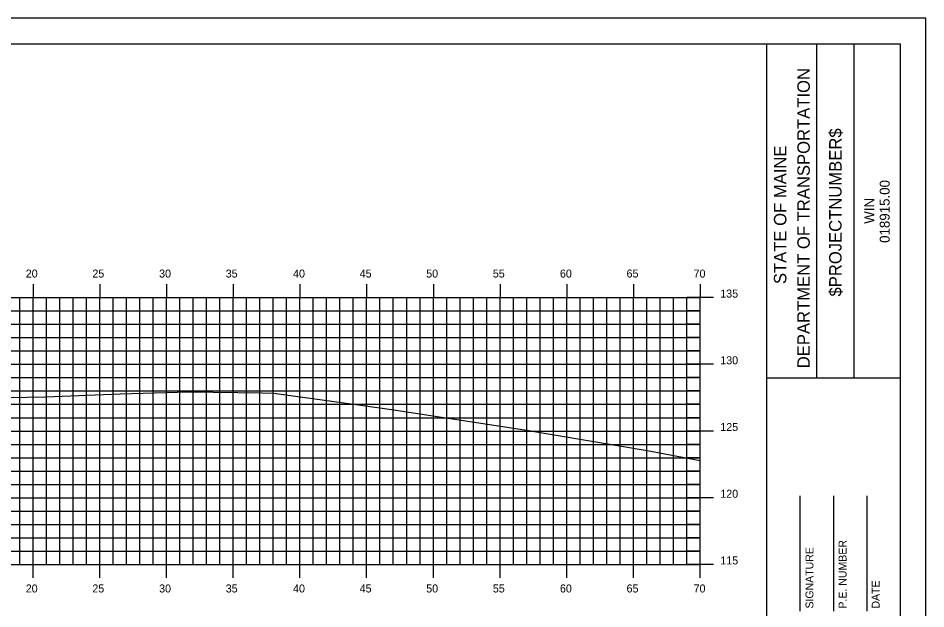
# Model space of a CAD drawing. Extents: x 851517 to 851688, y 365624 to 365734.
# Drawn here: x 851618.7 to 851686.7, y 365689.7 to 365734 of the extents above; entities that cross this region are included whole.
import ezdxf

# ---------------------------------------------------------------- set-up
doc = ezdxf.new("R2010")
doc.units = 0
for name, color, linetype in [('BORDER', 7, 'Continuous'), ('H_V ANNOTATION', 7, 'Continuous'), ('MAJOR', 7, 'Continuous'), ('MINOR', 7, 'Continuous'), ('PLOT BOUNDARY', 7, 'Continuous'), ('S_Roadway_Centerline', 7, 'Continuous')]:
    doc.layers.add(name, color=color, linetype=linetype)

msp = doc.modelspace()

# ---------------------------------------------------------------- linework, layer by layer
at = {"layer": 'BORDER'}
for p, q in [((851674.766, 365627.027), (851674.766, 365732.027)), ((851678.494, 365707.024), (851678.494, 365732.024)), ((851681.289, 365707.024), (851681.289, 365732.024)), ((851674.767, 365707.021), (851684.766, 365707.021)), ((851677.266, 365689.53), (851677.266, 365698.177)), ((851679.766, 365689.53), (851679.766, 365698.177)), ((851682.266, 365689.53), (851682.266, 365698.177))]:
    msp.add_line(p, q, dxfattribs=at)
msp.add_lwpolyline([(851524.766, 365627.027), (851684.766, 365627.027), (851684.766, 365732.027), (851524.766, 365732.027)], close=True, dxfattribs=at)
at = {"layer": 'MAJOR'}
for p, q in [((851619.766, 365714.029), (851619.766, 365713.027)), ((851624.766, 365714.029), (851624.766, 365713.027)), ((851629.766, 365714.029), (851629.766, 365713.027)), ((851634.766, 365714.029), (851634.766, 365713.027)), ((851639.766, 365714.029), (851639.766, 365713.027)), ((851644.766, 365714.029), (851644.766, 365713.027)), ((851649.766, 365714.029), (851649.766, 365713.027)), ((851654.766, 365714.029), (851654.766, 365713.027)), ((851659.766, 365714.029), (851659.766, 365713.027)), ((851664.766, 365714.029), (851664.766, 365713.027)), ((851669.766, 365714.029), (851669.766, 365713.027)), ((851529.766, 365713.027), (851669.766, 365713.027)), ((851529.766, 365713.027), (851669.766, 365713.027)), ((851619.766, 365693.027), (851619.766, 365713.027)), ((851624.766, 365693.027), (851624.766, 365713.027)), ((851629.766, 365693.027), (851629.766, 365713.027)), ((851634.766, 365693.027), (851634.766, 365713.027)), ((851639.766, 365693.027), (851639.766, 365713.027)), ((851644.766, 365693.027), (851644.766, 365713.027)), ((851649.766, 365693.027), (851649.766, 365713.027)), ((851654.766, 365693.027), (851654.766, 365713.027)), ((851659.766, 365693.027), (851659.766, 365713.027)), ((851664.766, 365693.027), (851664.766, 365713.027)), ((851670.768, 365713.027), (851668.764, 365713.027)), ((851669.766, 365693.027), (851669.766, 365713.027)), ((851669.766, 365693.027), (851669.766, 365713.027)), ((851529.766, 365708.027), (851669.766, 365708.027)), ((851670.768, 365708.027), (851668.764, 365708.027)), ((851529.766, 365703.027), (851669.766, 365703.027)), ((851670.768, 365703.027), (851668.764, 365703.027)), ((851529.766, 365698.027), (851669.766, 365698.027)), ((851670.768, 365698.027), (851668.764, 365698.027)), ((851529.766, 365693.027), (851669.766, 365693.027)), ((851529.766, 365693.027), (851669.766, 365693.027)), ((851619.766, 365692.025), (851619.766, 365693.027)), ((851624.766, 365692.025), (851624.766, 365693.027)), ((851629.766, 365692.025), (851629.766, 365693.027)), ((851634.766, 365692.025), (851634.766, 365693.027)), ((851639.766, 365692.025), (851639.766, 365693.027)), ((851644.766, 365692.025), (851644.766, 365693.027)), ((851649.766, 365692.025), (851649.766, 365693.027)), ((851654.766, 365692.025), (851654.766, 365693.027)), ((851659.766, 365692.025), (851659.766, 365693.027)), ((851664.766, 365692.025), (851664.766, 365693.027)), ((851670.768, 365693.027), (851668.764, 365693.027)), ((851669.766, 365692.025), (851669.766, 365693.027))]:
    msp.add_line(p, q, dxfattribs=at)
at = {"layer": 'MINOR'}
for p, q in [((851618.766, 365693.027), (851618.766, 365713.027)), ((851620.766, 365693.027), (851620.766, 365713.027)), ((851621.766, 365693.027), (851621.766, 365713.027)), ((851622.766, 365693.027), (851622.766, 365713.027)), ((851623.766, 365693.027), (851623.766, 365713.027)), ((851625.766, 365693.027), (851625.766, 365713.027)), ((851626.766, 365693.027), (851626.766, 365713.027)), ((851627.766, 365693.027), (851627.766, 365713.027)), ((851628.766, 365693.027), (851628.766, 365713.027)), ((851630.766, 365693.027), (851630.766, 365713.027)), ((851631.766, 365693.027), (851631.766, 365713.027)), ((851632.766, 365693.027), (851632.766, 365713.027)), ((851633.766, 365693.027), (851633.766, 365713.027)), ((851635.766, 365693.027), (851635.766, 365713.027)), ((851636.766, 365693.027), (851636.766, 365713.027)), ((851637.766, 365693.027), (851637.766, 365713.027)), ((851638.766, 365693.027), (851638.766, 365713.027)), ((851640.766, 365693.027), (851640.766, 365713.027)), ((851641.766, 365693.027), (851641.766, 365713.027)), ((851642.766, 365693.027), (851642.766, 365713.027)), ((851643.766, 365693.027), (851643.766, 365713.027)), ((851645.766, 365693.027), (851645.766, 365713.027)), ((851646.766, 365693.027), (851646.766, 365713.027)), ((851647.766, 365693.027), (851647.766, 365713.027)), ((851648.766, 365693.027), (851648.766, 365713.027)), ((851650.766, 365693.027), (851650.766, 365713.027)), ((851651.766, 365693.027), (851651.766, 365713.027)), ((851652.766, 365693.027), (851652.766, 365713.027)), ((851653.766, 365693.027), (851653.766, 365713.027)), ((851655.766, 365693.027), (851655.766, 365713.027)), ((851656.766, 365693.027), (851656.766, 365713.027)), ((851657.766, 365693.027), (851657.766, 365713.027)), ((851658.766, 365693.027), (851658.766, 365713.027)), ((851660.766, 365693.027), (851660.766, 365713.027)), ((851661.766, 365693.027), (851661.766, 365713.027)), ((851662.766, 365693.027), (851662.766, 365713.027)), ((851663.766, 365693.027), (851663.766, 365713.027)), ((851665.766, 365693.027), (851665.766, 365713.027)), ((851666.766, 365693.027), (851666.766, 365713.027)), ((851667.766, 365693.027), (851667.766, 365713.027)), ((851668.766, 365693.027), (851668.766, 365713.027)), ((851529.766, 365712.027), (851669.766, 365712.027)), ((851669.766, 365712.027), (851668.764, 365712.027)), ((851529.766, 365711.027), (851669.766, 365711.027)), ((851669.766, 365711.027), (851668.764, 365711.027)), ((851529.766, 365710.027), (851669.766, 365710.027)), ((851669.766, 365710.027), (851668.764, 365710.027)), ((851529.766, 365709.027), (851669.766, 365709.027)), ((851669.766, 365709.027), (851668.764, 365709.027)), ((851529.766, 365707.027), (851669.766, 365707.027)), ((851669.766, 365707.027), (851668.764, 365707.027)), ((851529.766, 365706.027), (851669.766, 365706.027)), ((851669.766, 365706.027), (851668.764, 365706.027)), ((851529.766, 365705.027), (851669.766, 365705.027)), ((851669.766, 365705.027), (851668.764, 365705.027)), ((851529.766, 365704.027), (851669.766, 365704.027)), ((851669.766, 365704.027), (851668.764, 365704.027)), ((851529.766, 365702.027), (851669.766, 365702.027)), ((851669.766, 365702.027), (851668.764, 365702.027)), ((851529.766, 365701.027), (851669.766, 365701.027)), ((851669.766, 365701.027), (851668.764, 365701.027)), ((851529.766, 365700.027), (851669.766, 365700.027)), ((851669.766, 365700.027), (851668.764, 365700.027)), ((851529.766, 365699.027), (851669.766, 365699.027)), ((851669.766, 365699.027), (851668.764, 365699.027)), ((851529.766, 365697.027), (851669.766, 365697.027)), ((851669.766, 365697.027), (851668.764, 365697.027)), ((851529.766, 365696.027), (851669.766, 365696.027)), ((851669.766, 365696.027), (851668.764, 365696.027)), ((851529.766, 365695.027), (851669.766, 365695.027)), ((851669.766, 365695.027), (851668.764, 365695.027)), ((851529.766, 365694.027), (851669.766, 365694.027)), ((851669.766, 365694.027), (851668.764, 365694.027))]:
    msp.add_line(p, q, dxfattribs=at)
at = {"layer": 'PLOT BOUNDARY'}
msp.add_lwpolyline([(851516.673, 365623.968), (851686.673, 365623.968), (851686.673, 365733.968), (851516.673, 365733.968)], close=True, dxfattribs=at)
at = {"layer": 'S_Roadway_Centerline'}
msp.add_lwpolyline([(851617.951, 365705.528), (851620.707, 365705.594), (851626.295, 365705.822), (851631.43, 365705.968), (851636.946, 365705.887), (851637.814, 365705.858), (851644.508, 365704.946), (851646.629, 365704.649), (851656.605, 365703.12), (851665.78, 365701.579), (851669.766, 365700.806)], dxfattribs=at)

# ---------------------------------------------------------------- texts
at = {"layer": 'BORDER'}
for s, height, p in [('DEPARTMENT OF TRANSPORTATION', 0.93176, (851677.973, 365707.733)), ('$PROJECTNUMBER$', 0.93176, (851680.358, 365713.106)), ('STATE OF MAINE', 0.93176, (851676.221, 365714.039)), ('018915.00', 0.7453, (851683.961, 365717.125)), ('WIN', 0.7453, (851682.803, 365718.557)), ('P.E. NUMBER', 0.59055, (851680.727, 365689.722)), ('SIGNATURE', 0.5906, (851678.246, 365689.722)), ('DATE', 0.5906, (851683.207, 365689.722))]:
    msp.add_text(s, height=height, rotation=90, dxfattribs=at).set_placement(p)
at = {"layer": 'H_V ANNOTATION'}
for s, p in [('20', (851619.22, 365714.527)), ('25', (851624.212, 365714.527)), ('30', (851629.214, 365714.527)), ('35', (851634.206, 365714.527)), ('40', (851639.252, 365714.527)), ('45', (851644.244, 365714.527)), ('50', (851649.23, 365714.527)), ('55', (851654.222, 365714.527)), ('60', (851659.252, 365714.527)), ('65', (851664.244, 365714.527)), ('70', (851669.268, 365714.527)), ('135', (851671.266, 365713.027)), ('130', (851671.266, 365708.027)), ('125', (851671.266, 365703.027)), ('120', (851671.266, 365698.027)), ('115', (851671.266, 365693.027)), ('20', (851619.22, 365690.927)), ('25', (851624.212, 365690.927)), ('30', (851629.214, 365690.927)), ('35', (851634.206, 365690.927)), ('40', (851639.252, 365690.927)), ('45', (851644.244, 365690.927)), ('50', (851649.23, 365690.927)), ('55', (851654.222, 365690.927)), ('60', (851659.252, 365690.927)), ('65', (851664.244, 365690.927)), ('70', (851669.268, 365690.927))]:
    msp.add_text(s, height=0.6, dxfattribs=at).set_placement(p)

doc.saveas('drawing.dxf')
